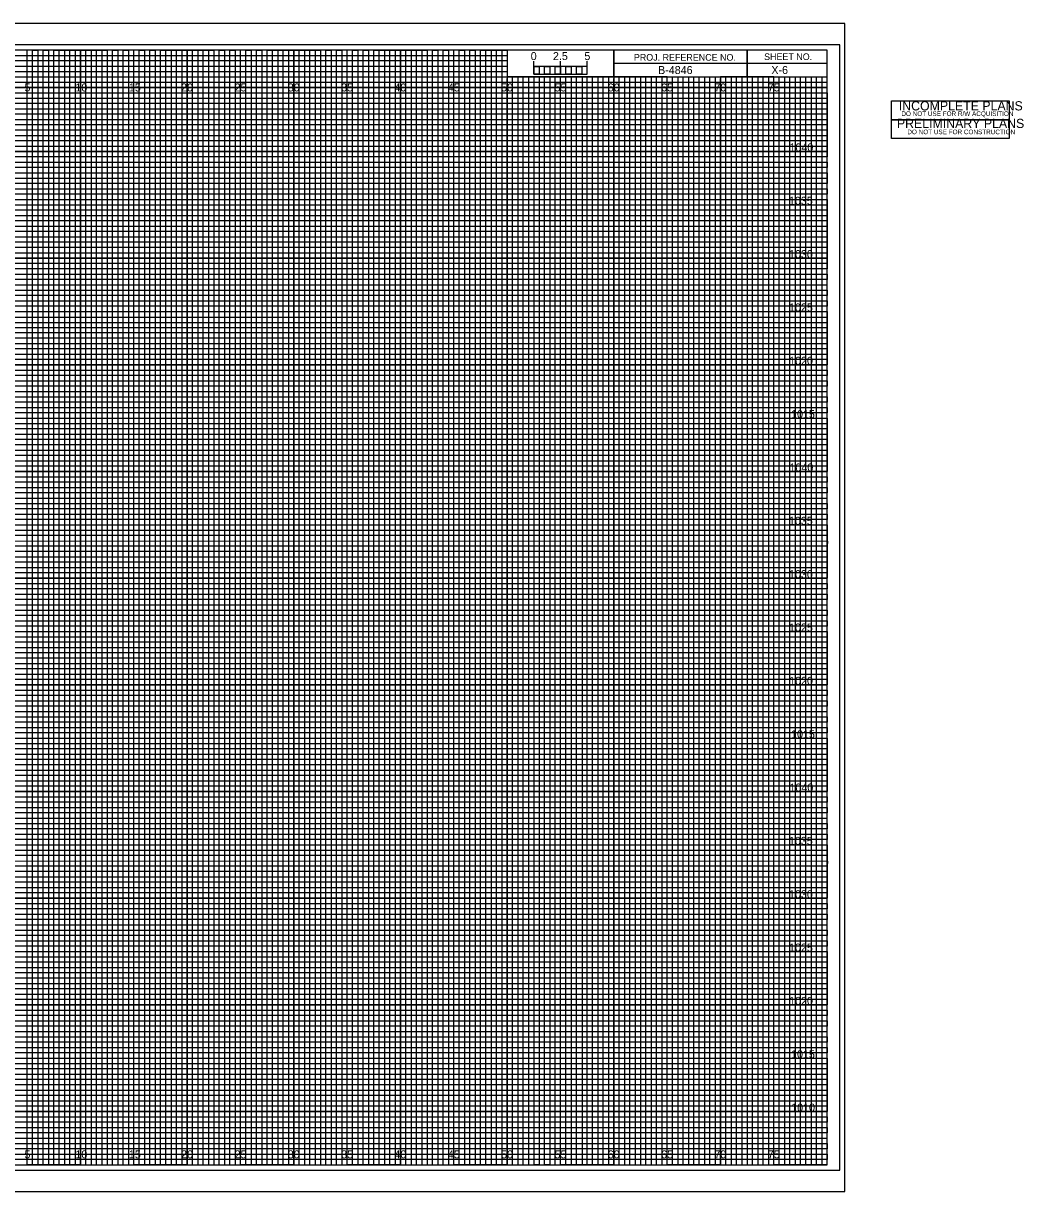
# Model space of a CAD drawing. Extents: x -7 to 178, y 548 to 657.
# Drawn here: x 84.6 to 178.4, y 547.5 to 657 of the extents above; entities that cross this region are included whole.
import ezdxf

# ---------------------------------------------------------------- set-up
doc = ezdxf.new("R2010")
doc.units = 0
for name, color, linetype in [('Default', 7, 'Continuous'), ('Exist Cross Section Cell', 7, 'Continuous'), ('Exist XS Center Line Elevation Label', 7, 'Continuous'), ('Exist XS Ground Line', 7, 'Continuous'), ('Prop CMT Concrete Structures', 7, 'Continuous'), ('Prop CMT Guardrail Graphics', 7, 'Continuous'), ('Prop CMT Guardrail Widen Shoulder', 7, 'Continuous'), ('Prop CMT Pvmt Course 1', 7, 'Continuous'), ('Prop CMT Pvmt Surface', 7, 'Continuous'), ('Prop CMT Pvmt Surface Shoulder', 7, 'Continuous'), ('Prop CMT Shld Paved Course 1', 7, 'Continuous'), ('Prop CMT Shoulder Point', 7, 'Continuous'), ('Prop CMT Slope Grass', 7, 'Continuous'), ('Prop CMT Subgrade Earthwork', 7, 'Continuous'), ('Prop XS SE Text', 7, 'Continuous'), ('Typical Text Label CELL', 7, 'Continuous')]:
    doc.layers.add(name, color=color, linetype=linetype)

msp = doc.modelspace()

# ---------------------------------------------------------------- linework, layer by layer
at = {"layer": 'Default'}
for points in [[(166.05, 647.97), (166.05, 649.73), (177.07, 649.73), (177.07, 647.97)], [(166.05, 646.2), (166.05, 647.97), (177.07, 647.97), (177.07, 646.2)]]:
    msp.add_lwpolyline(points, close=True, dxfattribs=at)
at = {"layer": 'Exist XS Center Line Elevation Label'}
for points in [[(82.5, 550), (87.5, 550), (87.5, 654.5), (92.5, 654.5), (92.5, 550), (97.5, 550), (97.5, 654.5), (102.5, 654.5), (102.5, 550), (107.5, 550), (107.5, 654.5), (112.5, 654.5), (112.5, 550), (117.5, 550), (117.5, 654.5), (122.5, 654.5), (122.5, 550), (127.5, 550), (127.5, 654.5), (129.97, 654.5), (130, 654.5), (130, 652), (132.5, 652), (132.5, 550), (137.5, 550), (137.5, 652), (142.5, 652), (142.5, 550), (147.5, 550), (147.5, 652), (152.5, 652), (152.5, 550), (157.5, 550), (157.5, 652)], [(0, 652), (137.5, 652)], [(0, 642.5), (160, 642.5), (160, 647.5), (0, 647.5)], [(0, 632.5), (160, 632.5), (160, 637.5), (0, 637.5)], [(0, 622.5), (160, 622.5), (160, 627.5), (0, 627.5)], [(0, 612.5), (160, 612.5), (160, 617.5), (0, 617.5)], [(0, 602.5), (160, 602.5), (160, 607.5), (0, 607.5)], [(0, 592.5), (160, 592.5), (160, 597.5), (0, 597.5)], [(0, 582.5), (160, 582.5), (160, 587.5), (0, 587.5)], [(0, 572.5), (160, 572.5), (160, 577.5), (0, 577.5)], [(0, 562.5), (160, 562.5), (160, 567.5), (0, 567.5)], [(0, 552.5), (160, 552.5), (160, 557.5), (0, 557.5)]]:
    msp.add_lwpolyline(points, dxfattribs=at)
at = {"layer": 'Exist XS Ground Line'}
for p, q in [((85, 654.5), (80, 654.5)), ((85, 550), (85, 654.5)), ((95, 654.5), (90, 654.5)), ((90, 654.5), (90, 550)), ((95, 550), (95, 654.5)), ((105, 654.5), (100, 654.5)), ((100, 654.5), (100, 550)), ((105, 550), (105, 654.5)), ((115, 654.5), (110, 654.5)), ((110, 654.5), (110, 550)), ((115, 550), (115, 654.5)), ((125, 654.5), (120, 654.5)), ((120, 654.5), (120, 550)), ((125, 550), (125, 654.5)), ((130, 654.5), (130, 550)), ((135, 550), (135, 652)), ((145, 652), (140, 652)), ((140, 652), (140, 550)), ((145, 550), (145, 652)), ((155, 652), (150, 652)), ((150, 652), (150, 550)), ((155, 550), (155, 652)), ((90, 550), (85, 550)), ((100, 550), (95, 550)), ((110, 550), (105, 550)), ((120, 550), (115, 550)), ((130, 550), (125, 550)), ((140, 550), (135, 550)), ((150, 550), (145, 550)), ((160, 550), (155, 550)), ((160, 550), (160, 550))]:
    msp.add_line(p, q, dxfattribs=at)
for points in [[(0, 650), (160, 650), (160, 645), (0, 645)], [(0, 640), (160, 640), (160, 635), (0, 635)], [(0, 630), (160, 630), (160, 625), (0, 625)], [(0, 620), (160, 620), (160, 615), (0, 615)], [(0, 610), (160, 610), (160, 605), (0, 605)], [(0, 600), (160, 600), (160, 595), (0, 595)], [(0, 590), (160, 590), (160, 585), (0, 585)], [(0, 580), (160, 580), (160, 575), (0, 575)], [(0, 570), (160, 570), (160, 565), (0, 565)], [(0, 560), (160, 560), (160, 555), (0, 555)]]:
    msp.add_lwpolyline(points, dxfattribs=at)
at = {"layer": 'Prop CMT Concrete Structures'}
for p, q in [((85, 550), (85, 654.5)), ((90, 550), (90, 654.5)), ((95, 550), (95, 654.5)), ((100, 550), (100, 654.5)), ((105, 550), (105, 654.5)), ((110, 550), (110, 654.5)), ((115, 550), (115, 654.5)), ((120, 550), (120, 654.5)), ((125, 550), (125, 654.5)), ((130, 550), (130, 651.84)), ((135, 550), (135, 651.84)), ((140, 550), (140, 651.84)), ((145, 550), (145, 651.84)), ((150, 550), (150, 651.84)), ((155, 550), (155, 651.84)), ((0, 650), (160, 650)), ((0, 645), (160, 645)), ((0, 640), (160, 640)), ((0, 635), (160, 635)), ((0, 630), (160, 630)), ((0, 625), (160, 625)), ((0, 620), (160, 620)), ((0, 615), (160, 615)), ((0, 610), (160, 610)), ((0, 605), (160, 605)), ((0, 600), (160, 600)), ((0, 595), (160, 595)), ((0, 590), (160, 590)), ((0, 585), (160, 585)), ((0, 580), (160, 580)), ((0, 575), (160, 575)), ((0, 570), (160, 570)), ((0, 565), (160, 565)), ((0, 560), (160, 560)), ((0, 555), (160, 555))]:
    msp.add_line(p, q, dxfattribs=at)
at = {"layer": 'Prop CMT Guardrail Widen Shoulder'}
for p, q in [((161.65, 657), (-6.7, 657)), ((-6.7, 547.5), (161.65, 547.5))]:
    msp.add_line(p, q, dxfattribs=at)
at = {"layer": 'Prop CMT Pvmt Course 1'}
msp.add_lwpolyline([(-6.7, 547.5), (161.65, 547.5), (161.65, 657), (-6.7, 657)], close=True, dxfattribs=at)
at = {"layer": 'Prop CMT Pvmt Surface'}
for p, q in [((133.5, 652), (133, 652)), ((133, 652), (133, 550)), ((133.5, 550), (133.5, 652)), ((134.5, 652), (134, 652)), ((134, 652), (134, 550)), ((134.5, 550), (134.5, 652)), ((133, 550), (132.5, 550)), ((134, 550), (133.5, 550))]:
    msp.add_line(p, q, dxfattribs=at)
for points in [[(85, 550), (85.5, 550), (85.5, 654.5), (86, 654.5), (86, 550)], [(86, 550), (86.5, 550), (86.5, 654.5), (87, 654.5), (87, 550)], [(87.5, 550), (88, 550), (88, 654.5), (88.5, 654.5), (88.5, 550)], [(88.5, 550), (89, 550), (89, 654.5), (89.5, 654.5), (89.5, 550)], [(90, 550), (90.5, 550), (90.5, 654.5), (91, 654.5), (91, 550)], [(91, 550), (91.5, 550), (91.5, 654.5), (92, 654.5), (92, 550)], [(92.5, 550), (93, 550), (93, 654.5), (93.5, 654.5), (93.5, 550)], [(93.5, 550), (94, 550), (94, 654.5), (94.5, 654.5), (94.5, 550)], [(95, 550), (95.5, 550), (95.5, 654.5), (96, 654.5), (96, 550)], [(96, 550), (96.5, 550), (96.5, 654.5), (97, 654.5), (97, 550)], [(97.5, 550), (98, 550), (98, 654.5), (98.5, 654.5), (98.5, 550)], [(98.5, 550), (99, 550), (99, 654.5), (99.5, 654.5), (99.5, 550)], [(100, 550), (100.5, 550), (100.5, 654.5), (101, 654.5), (101, 550)], [(101, 550), (101.5, 550), (101.5, 654.5), (102, 654.5), (102, 550)], [(102.5, 550), (103, 550), (103, 654.5), (103.5, 654.5), (103.5, 550)], [(103.5, 550), (104, 550), (104, 654.5), (104.5, 654.5), (104.5, 550)], [(105, 550), (105.5, 550), (105.5, 654.5), (106, 654.5), (106, 550)], [(106, 550), (106.5, 550), (106.5, 654.5), (107, 654.5), (107, 550)], [(107.5, 550), (108, 550), (108, 654.5), (108.5, 654.5), (108.5, 550)], [(108.5, 550), (109, 550), (109, 654.5), (109.5, 654.5), (109.5, 550)], [(110, 550), (110.5, 550), (110.5, 654.5), (111, 654.5), (111, 550)], [(111, 550), (111.5, 550), (111.5, 654.5), (112, 654.5), (112, 550)], [(112.5, 550), (113, 550), (113, 654.5), (113.5, 654.5), (113.5, 550)], [(113.5, 550), (114, 550), (114, 654.5), (114.5, 654.5), (114.5, 550)], [(115, 550), (115.5, 550), (115.5, 654.5), (116, 654.5), (116, 550)], [(116, 550), (116.5, 550), (116.5, 654.5), (117, 654.5), (117, 550)], [(117.5, 550), (118, 550), (118, 654.5), (118.5, 654.5), (118.5, 550)], [(118.5, 550), (119, 550), (119, 654.5), (119.5, 654.5), (119.5, 550)], [(120, 550), (120.5, 550), (120.5, 654.5), (121, 654.5), (121, 550)], [(121, 550), (121.5, 550), (121.5, 654.5), (122, 654.5), (122, 550)], [(122.5, 550), (123, 550), (123, 654.5), (123.5, 654.5), (123.5, 550)], [(123.5, 550), (124, 550), (124, 654.5), (124.5, 654.5), (124.5, 550)], [(125, 550), (125.5, 550), (125.5, 654.5), (126, 654.5), (126, 550)], [(126, 550), (126.5, 550), (126.5, 654.5), (127, 654.5), (127, 550)], [(127.5, 550), (128, 550), (128, 654.5), (128.5, 654.5), (128.5, 550)], [(128.5, 550), (129, 550), (129, 654.5), (129.5, 654.5), (129.5, 550)], [(130, 550), (130.5, 550), (130.5, 652), (131.01, 652), (131.01, 550)], [(131, 550), (131.5, 550), (131.5, 652), (132, 652), (132, 550)], [(135, 550), (135.49, 550), (135.49, 652), (136, 652), (136, 550)], [(136, 550), (136.5, 550), (136.5, 652), (137.03, 652), (137.03, 550)], [(137.5, 550), (138, 550), (138, 652), (138.5, 652), (138.5, 550)], [(138.5, 550), (139, 550), (139, 652), (139.5, 652), (139.5, 550)], [(140, 550), (140.5, 550), (140.5, 652), (141, 652), (141, 550)], [(141, 550), (141.5, 550), (141.5, 652), (142, 652), (142, 550)], [(142.5, 550), (143, 550), (143, 652), (143.5, 652), (143.5, 550)], [(143.5, 550), (144, 550), (144, 652), (144.5, 652), (144.5, 550)], [(145, 550), (145.5, 550), (145.5, 652), (146, 652), (146, 550)], [(146, 550), (146.5, 550), (146.5, 652), (147, 652), (147, 550)], [(147.5, 550), (148, 550), (148, 652), (148.5, 652), (148.5, 550)], [(148.5, 550), (149, 550), (149, 652), (149.5, 652), (149.5, 550)], [(150, 550), (150.5, 550), (150.5, 652), (151, 652), (151, 550)], [(151, 550), (151.5, 550), (151.5, 652), (152, 652), (152, 550)], [(152.5, 550), (153, 550), (153, 652), (153.5, 652), (153.5, 550)], [(153.5, 550), (154, 550), (154, 652), (154.5, 652), (154.5, 550)], [(155, 550), (155.5, 550), (155.5, 652), (156, 652), (156, 550)], [(156, 550), (156.5, 550), (156.5, 652), (157, 652), (157, 550)], [(157.5, 550), (158, 550), (158, 652), (158.5, 652), (158.5, 550)], [(158.5, 550), (159, 550), (159, 652), (159.5, 652), (159.5, 550)]]:
    msp.add_lwpolyline(points, dxfattribs=at)
at = {"layer": 'Prop CMT Pvmt Surface Shoulder'}
for p, q in [((132.5, 652.25), (132.5, 653.45)), ((132.5, 652.95), (132.5, 653.45)), ((135, 652.25), (135, 653.45)), ((137.5, 652.25), (137.5, 653.45)), ((137.5, 652.95), (137.5, 653.45))]:
    msp.add_line(p, q, dxfattribs=at)
for points in [[(137.5, 652.95), (132.5, 652.95), (132.5, 652.25), (137.5, 652.25)], [(132.5, 652.95), (133, 652.95), (133, 652.25), (132.5, 652.25)], [(133.5, 652.95), (134, 652.95), (134, 652.25), (133.5, 652.25)], [(134.5, 652.95), (135, 652.95), (135, 652.25), (134.5, 652.25)], [(135.5, 652.95), (136, 652.95), (136, 652.25), (135.5, 652.25)], [(136.5, 652.95), (137, 652.95), (137, 652.25), (136.5, 652.25)]]:
    msp.add_lwpolyline(points, close=True, dxfattribs=at)
at = {"layer": 'Prop CMT Shld Paved Course 1'}
for p, q in [((0, 654), (130, 654)), ((130, 654), (130, 653.49)), ((130, 653.49), (0, 653.49)), ((0, 653), (130, 653)), ((130, 653), (130, 652.45)), ((130, 652.45), (0, 652.45)), ((0, 651.5), (160, 651.5))]:
    msp.add_line(p, q, dxfattribs=at)
for points in [[(0, 651), (135, 651), (160, 651), (160, 651), (0, 651)], [(0, 650.5), (160, 650.5), (160, 649.5), (0, 649.5)], [(0, 649), (160, 649), (160, 648.5), (0, 648.49)], [(0, 648), (160, 648), (160, 647), (0, 647)], [(0, 646.5), (160, 646.5), (160, 646), (0, 646)], [(0, 645.5), (160, 645.5), (160, 644.5), (0, 644.5)], [(0, 644), (160, 644), (160, 643.5), (0, 643.5)], [(0, 643), (160, 643), (160, 642), (0, 642)], [(0, 641.5), (160, 641.5), (160, 641), (0, 641)], [(0, 640.5), (160, 640.5), (160, 639.5), (0, 639.5)], [(0, 639), (160, 639), (160, 638.5), (0, 638.5)], [(0, 638), (160, 638), (160, 636.98), (160, 636.5), (160, 636), (0, 636)], [(0, 637), (160, 637), (160, 636.5), (0, 636.5)], [(0, 635.5), (160, 635.5), (160, 634.5), (0, 634.51)], [(0, 634.51), (160, 634.5), (160, 634), (0, 634)], [(0, 633.5), (160, 633.5), (160, 633), (0, 633)], [(0, 632), (160, 632), (160, 631.5), (0, 631.5)], [(0, 631), (160, 631), (160, 630.5), (0, 630.5)], [(-0.04, 629.45), (160, 629.45), (160, 628.94), (-0.04, 628.94)], [(0, 628.5), (160, 628.5), (160, 628), (0, 628)], [(0, 627), (160, 627), (160, 626.5), (0, 626.5)], [(0, 626), (160, 626), (160, 625.5), (0, 625.5)], [(0, 624.5), (160, 624.5), (160, 624), (0, 624)], [(0, 623.5), (160, 623.5), (160, 623), (0, 623)], [(0, 622), (160, 622), (160, 621.5), (0, 621.5)], [(0, 621), (160, 621), (160, 620.5), (0, 620.5)], [(0, 619.5), (160, 619.5), (160, 618.99), (0, 619)], [(0, 618.5), (160, 618.5), (160, 618), (0, 618)], [(0, 617), (160, 617), (160, 616.5), (0, 616.5)], [(0, 616), (160, 616), (160, 615.5), (0, 615.5)], [(0, 614.5), (160, 614.5), (160, 614), (0, 614)], [(0, 613.5), (160, 613.5), (160, 613), (0, 613)], [(0, 612), (160, 612), (160, 611.5), (0, 611.5)], [(0, 611), (160, 611), (160, 610.5), (0, 610.5)], [(0, 609.5), (160, 609.5), (160, 609), (0, 609)], [(0, 608.5), (160.03, 608.46), (160, 608), (0, 608)], [(0, 607), (160, 607), (160, 606.5), (0, 606.5)], [(0, 606), (160, 606), (160, 605.5), (0, 605.5)], [(0, 604.5), (160, 604.5), (160, 604), (0, 604)], [(0, 603.5), (160, 603.5), (160, 603), (0, 603)], [(0, 602), (160, 602), (160, 601.5), (0, 601.5)], [(0, 601), (160, 601), (160, 600.5), (0, 600.5)], [(0, 599.5), (160, 599.5), (160, 599), (0, 599)], [(0, 598.5), (160, 598.5), (160, 598), (0, 598)], [(0, 597), (160, 597), (160, 596.5), (0, 596.5)], [(0, 596), (160, 596), (160, 595.5), (0, 595.5)], [(0, 594.5), (160, 594.5), (160, 594), (0, 594)], [(0, 593.5), (160, 593.5), (160, 593), (0, 593)], [(0, 592), (160, 592), (160, 591.5), (0, 591.5)], [(0, 591), (160, 591), (160, 590.5), (0, 590.5)], [(0, 589.5), (160, 589.5), (160, 588.99), (0, 589)], [(0, 588.5), (160, 588.5), (160, 588), (0, 588)], [(0, 587), (160, 587), (160, 586.5), (0, 586.5)], [(0, 586), (160, 586), (160, 585.5), (0, 585.5)], [(0, 584.5), (160, 584.5), (160, 584), (0, 584)], [(0, 583.5), (160, 583.5), (160, 583), (0, 583)], [(0, 582), (160, 582), (160, 581.5), (0, 581.5)], [(0, 581), (160, 581), (160, 580.5), (0, 580.5)], [(0, 579.5), (160, 579.5), (160, 579), (0, 579)], [(0, 578.5), (160.03, 578.46), (160, 578), (0, 578)], [(0, 577), (160, 577), (160, 576.5), (0, 576.5)], [(0, 576), (160, 576), (160, 575.5), (0, 575.5)], [(0, 574.5), (160, 574.5), (160, 574), (0, 574)], [(0, 573.5), (160, 573.5), (160, 573), (0, 573)], [(0, 572), (160, 572), (160, 571.5), (0, 571.5)], [(0, 571), (160, 571), (160, 570.5), (0, 570.5)], [(0, 569.5), (160, 569.5), (160, 569), (0, 569)], [(0, 568.5), (160, 568.5), (160, 568), (0, 568)], [(0, 567), (160, 567), (160, 566.5), (0, 566.5)], [(0, 566), (160, 566), (160, 565.5), (0, 565.5)], [(0, 564.5), (160, 564.5), (160, 564), (0, 564)], [(0, 563.5), (160, 563.5), (160, 563), (0, 563)], [(0, 562), (160, 562), (160, 561.5), (0, 561.5)], [(0, 561), (160, 561), (160, 560.5), (0, 560.5)], [(0, 559.5), (160, 559.5), (160, 559), (0, 559)], [(0, 558.5), (160, 558.5), (160, 558), (0, 558)], [(0, 557), (160, 557), (160, 556.5), (0, 556.5)], [(0, 556), (160, 556), (160, 555.5), (0, 555.5)], [(0, 554.5), (160, 554.5), (160, 554), (0, 554)], [(0, 553.5), (160, 553.5), (160, 553), (0, 553)], [(0, 552), (160, 552), (160, 551.5), (0, 551.5)], [(0, 551), (160, 551), (160, 550.5), (0, 550.5)]]:
    msp.add_lwpolyline(points, dxfattribs=at)
at = {"layer": 'Prop CMT Slope Grass'}
msp.add_lwpolyline([(-5.4, 549.5), (161.2, 549.5), (161.2, 655), (-5.4, 655)], close=True, dxfattribs=at)
at = {"layer": 'Prop CMT Subgrade Earthwork'}
for p, q in [((152.5, 654.5), (152.5, 652)), ((152.5, 652), (152.5, 654.5)), ((160, 653.25), (140, 653.25)), ((140, 653.25), (140, 652)), ((140, 652), (160, 652))]:
    msp.add_line(p, q, dxfattribs=at)
for points in [[(160, 654.5), (0, 654.5), (0, 550), (160, 550)], [(140, 654.5), (130, 654.5), (130, 652.01), (140, 652.01)], [(160, 654.5), (140, 654.5), (140, 652), (160, 652)]]:
    msp.add_lwpolyline(points, close=True, dxfattribs=at)

# ---------------------------------------------------------------- texts
at = {"layer": 'Default'}
for s, height, p in [('INCOMPLETE PLANS', 0.864, (166.72, 648.84)), ('DO NOT USE FOR R/W ACQUISITION', 0.432, (166.96, 648.32)), ('PRELIMINARY PLANS', 0.864, (166.54, 647.19)), ('DO NOT USE FOR CONSTRUCTION', 0.432, (167.52, 646.61))]:
    msp.add_text(s, height=height, dxfattribs=at).set_placement(p)
at = {"layer": 'Exist Cross Section Cell'}
for s, p in [('5', (84.74, 650.62)), ('10', (89.52, 650.62)), ('15', (94.53, 650.62)), ('20', (99.43, 650.62)), ('25', (104.44, 650.62)), ('30', (109.43, 650.62)), ('35', (114.44, 650.62)), ('40', (119.43, 650.62)), ('45', (124.44, 650.62)), ('50', (129.43, 650.62)), ('55', (134.44, 650.62)), ('60', (139.43, 650.62)), ('65', (144.44, 650.62)), ('70', (149.43, 650.62)), ('75', (154.44, 650.62)), ('5', (84.74, 550.62)), ('10', (89.52, 550.62)), ('15', (94.53, 550.62)), ('20', (99.43, 550.62)), ('25', (104.44, 550.62)), ('30', (109.43, 550.62)), ('35', (114.44, 550.62)), ('40', (119.43, 550.62)), ('45', (124.44, 550.62)), ('50', (129.43, 550.62)), ('55', (134.44, 550.62)), ('60', (139.43, 550.62)), ('65', (144.44, 550.62)), ('70', (149.43, 550.62)), ('75', (154.44, 550.62))]:
    msp.add_text(s, height=0.75, dxfattribs=at).set_placement(p)
at = {"layer": 'Prop CMT Guardrail Graphics'}
msp.add_text('B-4846', height=0.75, dxfattribs=at).set_placement((144.15, 652.25))
at = {"layer": 'Prop CMT Pvmt Surface Shoulder'}
msp.add_text('0', height=0.75, dxfattribs=at).set_placement((132.21, 653.56))
at = {"layer": 'Prop CMT Shoulder Point'}
for s, p in [('2.5', (134.29, 653.56)), ('5', (137.24, 653.56))]:
    msp.add_text(s, height=0.75, dxfattribs=at).set_placement(p)
at = {"layer": 'Prop CMT Subgrade Earthwork'}
for s, p in [('PROJ. REFERENCE NO.', (141.88, 653.5)), ('SHEET NO.', (154.09, 653.56))]:
    msp.add_text(s, height=0.625, dxfattribs=at).set_placement(p)
at = {"layer": 'Prop XS SE Text'}
msp.add_text('X-6', height=0.75, dxfattribs=at).set_placement((154.77, 652.25))
at = {"layer": 'Typical Text Label CELL'}
for s, p in [('1040', (156.47, 645)), ('1035', (156.42, 640)), ('1030', (156.43, 635)), ('1025', (156.43, 630)), ('1020', (156.44, 625)), ('1015', (156.62, 620)), ('1040', (156.47, 615)), ('1035', (156.42, 610)), ('1030', (156.43, 605)), ('1025', (156.43, 600)), ('1020', (156.44, 595)), ('1015', (156.62, 590)), ('1040', (156.47, 585)), ('1035', (156.42, 580)), ('1030', (156.43, 575)), ('1025', (156.43, 570)), ('1020', (156.44, 565)), ('1015', (156.62, 560)), ('1010', (156.63, 555))]:
    msp.add_text(s, height=0.75, dxfattribs=at).set_placement(p)

doc.saveas('drawing.dxf')
